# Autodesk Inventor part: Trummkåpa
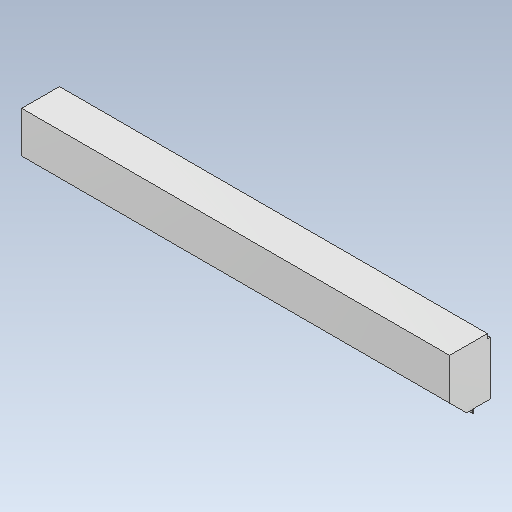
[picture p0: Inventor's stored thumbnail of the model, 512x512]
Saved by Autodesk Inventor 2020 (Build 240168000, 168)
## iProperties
Created: 2019-06
Part Number: Trummkåpa
Material: Aluminum
Document SubType Name: Modeling
Designer: cl
Density: 2.7 g/cm^3
Appearance: Satin
Author: cl
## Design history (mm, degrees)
sketch "Sketch1"
  geometry: L1 (0, 0)-(20, 0); L2 (20, 0)-(20, 32.56); L3 (20, 32.56)-(107.427, 119.987); L4 (107.427, 119.987)-(320.917, 119.987); L5 (320.917, 119.987)-(320.917, -75.013); L6 (320.917, -75.013)-(296.917, -75.013); L7 (296.917, -75.013)-(296.917, -90.013); L8 (296.917, -90.013)-(20.987, -90.013); L9 (0, 0)-(0, -2); L10 (0, -2)-(20.987, -2); L11 (20.987, -2)-(20.987, -90.013)
  constraints: 22 end point, 7 perpendicular, 1 horizontal, 1 parallel, 1 vertical
  dimensions: "d0" = 20 distance of L1.start L1.end; "d1" = 32.56 distance of L1.end L2.end; "d2" = 123.64 distance of L2.end L3.end; "d3" = 135 deg angle of L2 L3; "d4" = 213.49 distance of L3.end L4.end; "d5" = 195 distance of L4.end L5.end; "d6" = 24 distance of L5.end L6.end; "d7" = 15 distance of L6.end L7.end; "d8" = 275.93 distance of L7.end L8.end; "d10" = 2 distance of L1.start L9.end
extrude "Extrusion1" new body sketch "Sketch1" distance "d11" = 2210 (computed from Dagbredd); taper "d12" = 0 deg
body "Solid1"
